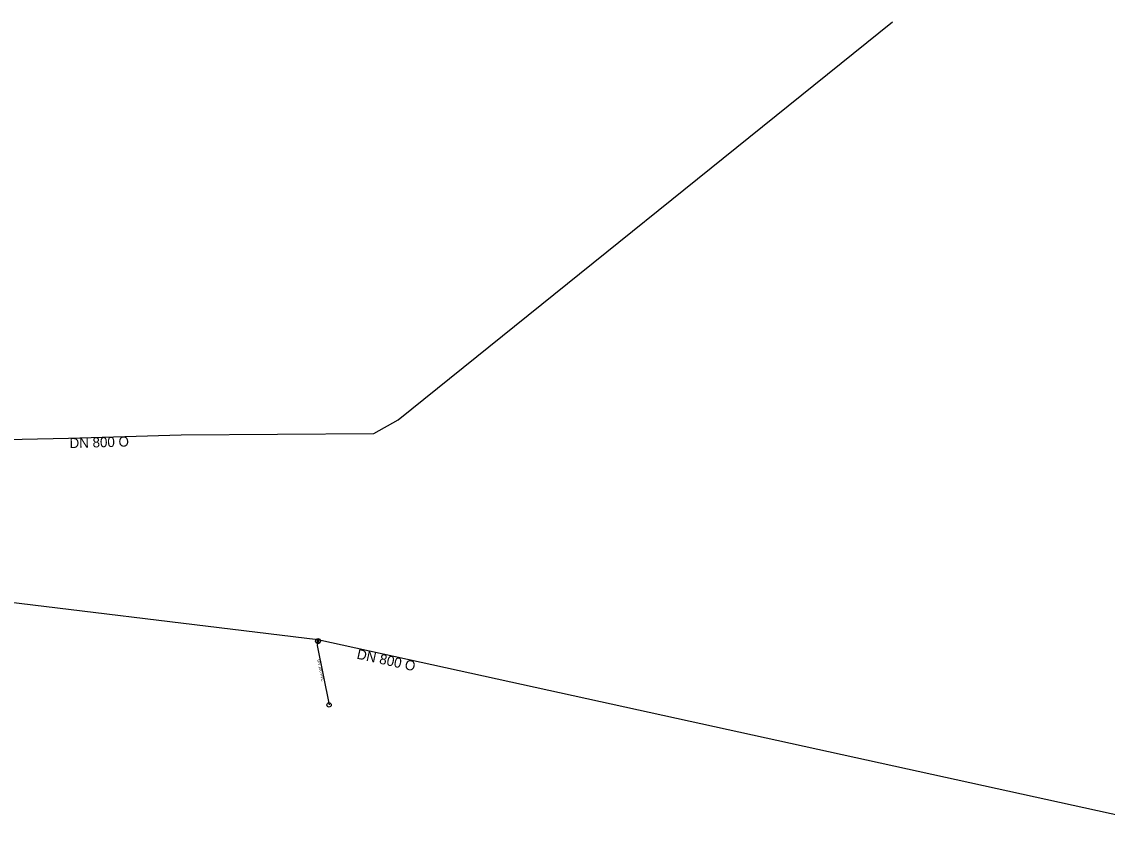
# Model space of a CAD drawing. Extents: x -451355 to -449353, y -1101368 to -1101089.
# Drawn here: x -449745.7 to -449571.2, y -1101281.4 to -1101152.8 of the extents above; entities that cross this region are included whole.
import ezdxf

# ---------------------------------------------------------------- set-up
doc = ezdxf.new("R2010")
doc.units = 0
for name, color, linetype in [('_pripojka_prevzato_z_dokumentace_', 7, 'Continuous'), ('_voda_smvak_prevzato_z_dokumentace_', 7, 'Continuous'), ('Default', 7, 'Continuous'), ('MoLevel 30', 7, 'Continuous'), ('MoLevel 46', 7, 'Continuous'), ('MoLevel 53', 7, 'Continuous'), ('MoLevel 55', 7, 'Continuous')]:
    doc.layers.add(name, color=color, linetype=linetype)

# ---------------------------------------------------------------- blocks, each defined once
blk = doc.blocks.new('_uzaver_pripojka_')
at = {"layer": 'Default'}
for p, q in [((-0.000035, -0.000035), (0.000035, 0.000035)), ((0.000035, -0.000035), (-0.000035, 0.000035))]:
    blk.add_line(p, q, dxfattribs=at)
for radius in [0.00005, 0.0000025]:
    blk.add_circle((0, 0), radius, dxfattribs=at)
blk = doc.blocks.new('_sachta_voda_')
at = {"layer": 'Default'}
blk.add_circle((0, 0), 0.000035, dxfattribs=at)

msp = doc.modelspace()

# ---------------------------------------------------------------- linework, layer by layer
at = {"layer": '_pripojka_prevzato_z_dokumentace_'}
msp.add_lwpolyline([(-449698.07, -1101252.11), (-449698.07, -1101252.29), (-449698.18, -1101252.99), (-449696.29, -1101262.55)], dxfattribs=at)
at = {"layer": '_voda_smvak_prevzato_z_dokumentace_'}
for points in [[(-449758.11, -1101220.11), (-449738.15, -1101219.69), (-449720.06, -1101219.18), (-449689.12, -1101218.97), (-449685.19, -1101216.75), (-449605.75, -1101152.8)], [(-449564.49, -1101281.4), (-449698.07, -1101252.11), (-449883.18, -1101229.61), (-449925.88, -1101227.01), (-449951.55, -1101226.31), (-449972.21, -1101225.79), (-449993.64, -1101225.6), (-450007.68, -1101225.99), (-450015.78, -1101225.72), (-450021.06, -1101225.6), (-450023.29, -1101225.59), (-450026.26, -1101226.9)]]:
    msp.add_lwpolyline(points, dxfattribs=at)

# ---------------------------------------------------------------- block references
at = {"layer": 'MoLevel 30', "xscale": 10000, "yscale": 10000}
msp.add_blockref('_sachta_voda_', (-449696.29, -1101262.55), dxfattribs=at)
at = {"layer": 'MoLevel 53', "xscale": 7999.999999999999, "yscale": 7999.999999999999}
msp.add_blockref('_uzaver_pripojka_', (-449698.07, -1101252.29), dxfattribs=at)

# ---------------------------------------------------------------- texts
at = {"layer": 'MoLevel 46'}
for rotation, p in [(1.6403, (-449737.98, -1101221.3)), (347.6325, (-449691.93, -1101255.1))]:
    msp.add_text('DN 800 O', height=1.605, rotation=rotation, dxfattribs=at).set_placement(p)
at = {"layer": 'MoLevel 55'}
msp.add_text('DN 100 PVC', height=0.455, rotation=281.1831, dxfattribs=at).set_placement((-449698.19, -1101255.28))

doc.saveas('drawing.dxf')
